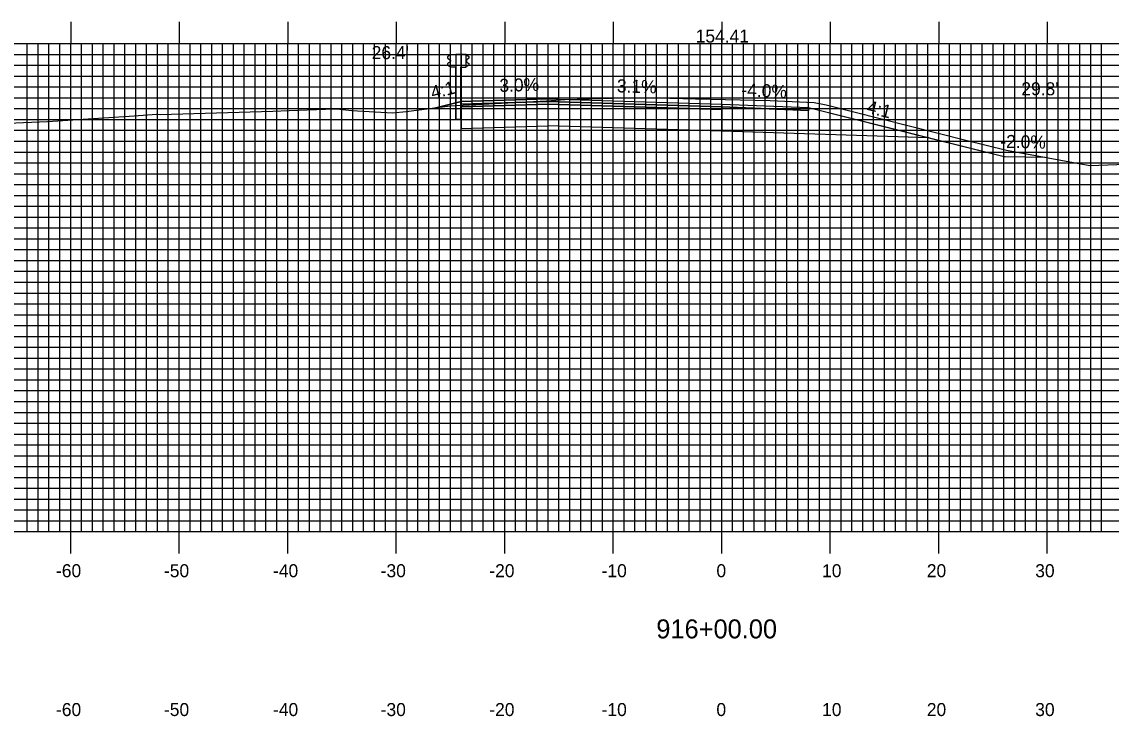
# Model space of a CAD drawing. Extents: x 861045 to 861388, y 364765 to 364985.
# Drawn here: x 861146.4 to 861246.8, y 364831.3 to 364895.3 of the extents above; entities that cross this region are included whole.
import ezdxf

# ---------------------------------------------------------------- set-up
doc = ezdxf.new("R2010")
doc.units = 0
for name, color, linetype in [('ANNOTATION', 7, 'Continuous'), ('D_Guardrail_Beam_Rt', 7, 'Continuous'), ('D_Roadway_Centerline', 7, 'Continuous'), ('D_Roadway_Centerline_Text', 7, 'Continuous'), ('D_Roadway_Edge_Shoulder', 7, 'Continuous'), ('D_Roadway_Edge_TW', 7, 'Continuous'), ('D_Roadway_Pavement', 7, 'Continuous'), ('D_Roadway_SlopeLines', 7, 'Continuous'), ('D_Roadway_SubGrade', 7, 'Continuous'), ('D_Text_Standard', 7, 'Continuous'), ('H_V ANNOTATION', 7, 'Continuous'), ('M_Guardrail', 7, 'Continuous'), ('M_Roadway_Centerline', 7, 'Continuous'), ('MAJOR', 7, 'Continuous'), ('MINOR', 7, 'Continuous'), ('S_Roadway_Centerline', 7, 'Continuous')]:
    doc.layers.add(name, color=color, linetype=linetype)

msp = doc.modelspace()

# ---------------------------------------------------------------- linework, layer by layer
at = {"layer": 'D_Guardrail_Beam_Rt'}
msp.add_line((861186.93, 364887.97), (861184.57, 364887.38), dxfattribs=at)
at = {"layer": 'D_Roadway_Centerline'}
msp.add_lwpolyline([(861184.57, 364887.38), (861186.93, 364887.97), (861189.93, 364888.06), (861194.93, 364888.21), (861194.93, 364888.21), (861210.93, 364887.71), (861218.93, 364887.39), (861219.43, 364887.27), (861230, 364884.62), (861230, 364884.62), (861236.97, 364882.88), (861237.05, 364882.88), (861240.75, 364882.81)], dxfattribs=at)
at = {"layer": 'D_Roadway_Edge_Shoulder'}
for points in [[(861194.93, 364888.21), (861189.93, 364888.06), (861186.93, 364887.97), (861186.93, 364887.72), (861194.93, 364887.96)], [(861210.93, 364887.71), (861218.93, 364887.39), (861218.93, 364887.14), (861210.93, 364887.46)]]:
    msp.add_lwpolyline(points, close=True, dxfattribs=at)
at = {"layer": 'D_Roadway_Edge_TW'}
msp.add_lwpolyline([(861194.93, 364888.21), (861210.93, 364887.71), (861210.93, 364887.46), (861194.93, 364887.96)], close=True, dxfattribs=at)
at = {"layer": 'D_Roadway_Pavement'}
for points in [[(861194.93, 364887.96), (861186.93, 364887.72), (861186.93, 364887.47), (861194.93, 364887.71)], [(861194.93, 364887.96), (861210.93, 364887.46), (861210.93, 364887.21), (861194.93, 364887.71)]]:
    msp.add_lwpolyline(points, close=True, dxfattribs=at)
msp.add_lwpolyline([(861210.93, 364887.46), (861210.93, 364887.21)], dxfattribs=at)
msp.add_lwpolyline([(861210.93, 364887.46), (861210.93, 364887.21)], dxfattribs=at)
at = {"layer": 'D_Roadway_SlopeLines'}
for points in [[(861218.93, 364887.39), (861236.97, 364882.88)], [(861236.97, 364882.88), (861240.75, 364882.81)]]:
    msp.add_lwpolyline(points, dxfattribs=at)
at = {"layer": 'D_Roadway_SubGrade'}
for points in [[(861194.93, 364887.71), (861186.93, 364887.47), (861186.93, 364887.72), (861186.93, 364885.47), (861194.93, 364885.71)], [(861194.93, 364887.71), (861210.93, 364887.21), (861210.93, 364885.21), (861194.93, 364885.71)], [(861210.93, 364887.21), (861210.93, 364887.46), (861218.93, 364887.14), (861218.93, 364887.39), (861230, 364884.62), (861210.93, 364885.21)]]:
    msp.add_lwpolyline(points, close=True, dxfattribs=at)
at = {"layer": 'M_Guardrail'}
for p, q in [((861185.83, 364892.19), (861185.69, 364892.09)), ((861185.69, 364891.95), (861185.88, 364891.81)), ((861185.88, 364891.59), (861185.69, 364891.46)), ((861185.93, 364892.21), (861185.85, 364892.2)), ((861185.92, 364891.75), (861185.92, 364891.66)), ((861185.93, 364892.29), (861186.42, 364892.29)), ((861185.93, 364891.12), (861185.93, 364892.29)), ((861186.41, 364892.29), (861186.41, 364886.29)), ((861186.9, 364892.29), (861186.41, 364892.29)), ((861186.42, 364892.29), (861186.91, 364892.29)), ((861186.42, 364892.29), (861186.42, 364891.12)), ((861187.39, 364892.29), (861186.9, 364892.29)), ((861186.9, 364892.29), (861186.9, 364891.12)), ((861186.91, 364892.29), (861186.91, 364886.29)), ((861187.39, 364891.12), (861187.39, 364892.29)), ((861187.39, 364892.21), (861187.47, 364892.2)), ((861187.4, 364891.75), (861187.4, 364891.66)), ((861187.63, 364891.95), (861187.43, 364891.81)), ((861187.43, 364891.59), (861187.63, 364891.46)), ((861187.49, 364892.19), (861187.63, 364892.09)), ((861185.69, 364891.31), (861185.83, 364891.21)), ((861185.85, 364891.21), (861185.93, 364891.19)), ((861186.42, 364891.12), (861185.93, 364891.12)), ((861186.42, 364886.29), (861186.42, 364891.12)), ((861186.9, 364886.29), (861186.9, 364891.12)), ((861186.9, 364891.12), (861187.39, 364891.12)), ((861187.47, 364891.21), (861187.39, 364891.19)), ((861187.63, 364891.32), (861187.49, 364891.22)), ((861186.9, 364886.29), (861186.41, 364886.29)), ((861186.42, 364886.29), (861186.91, 364886.29))]:
    msp.add_line(p, q, dxfattribs=at)
for centre, major_axis, start_param, end_param in [((861185.74, 364892.02), (-0.0877, 0), 5.323254, 7.243116), ((861185.85, 364892.16), (-0.0417, 0), 4.886922, 5.323254), ((861185.84, 364891.75), (0.0789, 0), 0, 0.959931), ((861185.84, 364891.66), (0.0789, 0), 5.323254, 6.283185), ((861187.48, 364891.75), (-0.0789, 0), 5.323254, 6.283185), ((861187.48, 364891.66), (-0.0789, 0), 6.283185, 7.243116), ((861187.46, 364892.16), (0.0417, 0), 0.959931, 1.396263), ((861187.58, 364892.02), (0.0877, 0), 5.323254, 7.243116), ((861185.74, 364891.39), (-0.0877, 0), 5.323254, 7.243116), ((861185.85, 364891.25), (-0.0417, 0), 0.959931, 1.396263), ((861187.46, 364891.25), (0.0417, 0), 4.886922, 5.323254), ((861187.58, 364891.39), (0.0877, 0), 5.323254, 7.243116)]:
    msp.add_ellipse(centre, major_axis=major_axis, ratio=0.995501, start_param=start_param, end_param=end_param, dxfattribs=at)
at = {"layer": 'MAJOR'}
for p, q in [((861150.93, 364895.31), (861150.93, 364893.3)), ((861160.93, 364895.31), (861160.93, 364893.3)), ((861170.93, 364895.31), (861170.93, 364893.3)), ((861180.93, 364895.31), (861180.93, 364893.3)), ((861190.93, 364895.31), (861190.93, 364893.3)), ((861200.93, 364895.31), (861200.93, 364893.3)), ((861210.93, 364895.31), (861210.93, 364893.3)), ((861220.93, 364895.31), (861220.93, 364893.3)), ((861230.93, 364895.31), (861230.93, 364893.3)), ((861240.93, 364895.31), (861240.93, 364893.3)), ((861070.93, 364893.3), (861350.93, 364893.3)), ((861070.93, 364893.3), (861350.93, 364893.3)), ((861150.93, 364848.3), (861150.93, 364893.3)), ((861160.93, 364848.3), (861160.93, 364893.3)), ((861170.93, 364848.3), (861170.93, 364893.3)), ((861180.93, 364848.3), (861180.93, 364893.3)), ((861190.93, 364848.3), (861190.93, 364893.3)), ((861200.93, 364848.3), (861200.93, 364893.3)), ((861210.93, 364848.3), (861210.93, 364893.3)), ((861220.93, 364848.3), (861220.93, 364893.3)), ((861230.93, 364848.3), (861230.93, 364893.3)), ((861240.93, 364848.3), (861240.93, 364893.3)), ((861070.93, 364888.3), (861350.93, 364888.3)), ((861070.93, 364883.3), (861350.93, 364883.3)), ((861070.93, 364878.3), (861350.93, 364878.3)), ((861070.93, 364873.3), (861350.93, 364873.3)), ((861070.93, 364868.3), (861350.93, 364868.3)), ((861070.93, 364863.3), (861350.93, 364863.3)), ((861070.93, 364858.3), (861350.93, 364858.3)), ((861070.93, 364853.3), (861350.93, 364853.3)), ((861070.93, 364848.3), (861350.93, 364848.3)), ((861070.93, 364848.3), (861350.93, 364848.3)), ((861150.93, 364846.3), (861150.93, 364848.3)), ((861160.93, 364846.3), (861160.93, 364848.3)), ((861170.93, 364846.3), (861170.93, 364848.3)), ((861180.93, 364846.3), (861180.93, 364848.3)), ((861190.93, 364846.3), (861190.93, 364848.3)), ((861200.93, 364846.3), (861200.93, 364848.3)), ((861210.93, 364846.3), (861210.93, 364848.3)), ((861220.93, 364846.3), (861220.93, 364848.3)), ((861230.93, 364846.3), (861230.93, 364848.3)), ((861240.93, 364846.3), (861240.93, 364848.3))]:
    msp.add_line(p, q, dxfattribs=at)
at = {"layer": 'MINOR'}
for p, q in [((861146.93, 364848.3), (861146.93, 364893.3)), ((861147.93, 364848.3), (861147.93, 364893.3)), ((861148.93, 364848.3), (861148.93, 364893.3)), ((861149.93, 364848.3), (861149.93, 364893.3)), ((861151.93, 364848.3), (861151.93, 364893.3)), ((861152.93, 364848.3), (861152.93, 364893.3)), ((861153.93, 364848.3), (861153.93, 364893.3)), ((861154.93, 364848.3), (861154.93, 364893.3)), ((861155.93, 364848.3), (861155.93, 364893.3)), ((861156.93, 364848.3), (861156.93, 364893.3)), ((861157.93, 364848.3), (861157.93, 364893.3)), ((861158.93, 364848.3), (861158.93, 364893.3)), ((861159.93, 364848.3), (861159.93, 364893.3)), ((861161.93, 364848.3), (861161.93, 364893.3)), ((861162.93, 364848.3), (861162.93, 364893.3)), ((861163.93, 364848.3), (861163.93, 364893.3)), ((861164.93, 364848.3), (861164.93, 364893.3)), ((861165.93, 364848.3), (861165.93, 364893.3)), ((861166.93, 364848.3), (861166.93, 364893.3)), ((861167.93, 364848.3), (861167.93, 364893.3)), ((861168.93, 364848.3), (861168.93, 364893.3)), ((861169.93, 364848.3), (861169.93, 364893.3)), ((861171.93, 364848.3), (861171.93, 364893.3)), ((861172.93, 364848.3), (861172.93, 364893.3)), ((861173.93, 364848.3), (861173.93, 364893.3)), ((861174.93, 364848.3), (861174.93, 364893.3)), ((861175.93, 364848.3), (861175.93, 364893.3)), ((861176.93, 364848.3), (861176.93, 364893.3)), ((861177.93, 364848.3), (861177.93, 364893.3)), ((861178.93, 364848.3), (861178.93, 364893.3)), ((861179.93, 364848.3), (861179.93, 364893.3)), ((861181.93, 364848.3), (861181.93, 364893.3)), ((861182.93, 364848.3), (861182.93, 364893.3)), ((861183.93, 364848.3), (861183.93, 364893.3)), ((861184.93, 364848.3), (861184.93, 364893.3)), ((861185.93, 364848.3), (861185.93, 364893.3)), ((861186.93, 364848.3), (861186.93, 364893.3)), ((861187.93, 364848.3), (861187.93, 364893.3)), ((861188.93, 364848.3), (861188.93, 364893.3)), ((861189.93, 364848.3), (861189.93, 364893.3)), ((861191.93, 364848.3), (861191.93, 364893.3)), ((861192.93, 364848.3), (861192.93, 364893.3)), ((861193.93, 364848.3), (861193.93, 364893.3)), ((861194.93, 364848.3), (861194.93, 364893.3)), ((861195.93, 364848.3), (861195.93, 364893.3)), ((861196.93, 364848.3), (861196.93, 364893.3)), ((861197.93, 364848.3), (861197.93, 364893.3)), ((861198.93, 364848.3), (861198.93, 364893.3)), ((861199.93, 364848.3), (861199.93, 364893.3)), ((861201.93, 364848.3), (861201.93, 364893.3)), ((861202.93, 364848.3), (861202.93, 364893.3)), ((861203.93, 364848.3), (861203.93, 364893.3)), ((861204.93, 364848.3), (861204.93, 364893.3)), ((861205.93, 364848.3), (861205.93, 364893.3)), ((861206.93, 364848.3), (861206.93, 364893.3)), ((861207.93, 364848.3), (861207.93, 364893.3)), ((861208.93, 364848.3), (861208.93, 364893.3)), ((861209.93, 364848.3), (861209.93, 364893.3)), ((861211.93, 364848.3), (861211.93, 364893.3)), ((861212.93, 364848.3), (861212.93, 364893.3)), ((861213.93, 364848.3), (861213.93, 364893.3)), ((861214.93, 364848.3), (861214.93, 364893.3)), ((861215.93, 364848.3), (861215.93, 364893.3)), ((861216.93, 364848.3), (861216.93, 364893.3)), ((861217.93, 364848.3), (861217.93, 364893.3)), ((861218.93, 364848.3), (861218.93, 364893.3)), ((861219.93, 364848.3), (861219.93, 364893.3)), ((861221.93, 364848.3), (861221.93, 364893.3)), ((861222.93, 364848.3), (861222.93, 364893.3)), ((861223.93, 364848.3), (861223.93, 364893.3)), ((861224.93, 364848.3), (861224.93, 364893.3)), ((861225.93, 364848.3), (861225.93, 364893.3)), ((861226.93, 364848.3), (861226.93, 364893.3)), ((861227.93, 364848.3), (861227.93, 364893.3)), ((861228.93, 364848.3), (861228.93, 364893.3)), ((861229.93, 364848.3), (861229.93, 364893.3)), ((861231.93, 364848.3), (861231.93, 364893.3)), ((861232.93, 364848.3), (861232.93, 364893.3)), ((861233.93, 364848.3), (861233.93, 364893.3)), ((861234.93, 364848.3), (861234.93, 364893.3)), ((861235.93, 364848.3), (861235.93, 364893.3)), ((861236.93, 364848.3), (861236.93, 364893.3)), ((861237.93, 364848.3), (861237.93, 364893.3)), ((861238.93, 364848.3), (861238.93, 364893.3)), ((861239.93, 364848.3), (861239.93, 364893.3)), ((861241.93, 364848.3), (861241.93, 364893.3)), ((861242.93, 364848.3), (861242.93, 364893.3)), ((861243.93, 364848.3), (861243.93, 364893.3)), ((861244.93, 364848.3), (861244.93, 364893.3)), ((861245.93, 364848.3), (861245.93, 364893.3)), ((861070.93, 364892.3), (861350.93, 364892.3)), ((861070.93, 364891.3), (861350.93, 364891.3)), ((861070.93, 364890.3), (861350.93, 364890.3)), ((861070.93, 364889.3), (861350.93, 364889.3)), ((861070.93, 364887.3), (861350.93, 364887.3)), ((861070.93, 364886.3), (861350.93, 364886.3)), ((861070.93, 364885.3), (861350.93, 364885.3)), ((861070.93, 364884.3), (861350.93, 364884.3)), ((861070.93, 364882.3), (861350.93, 364882.3)), ((861070.93, 364881.3), (861350.93, 364881.3)), ((861070.93, 364880.3), (861350.93, 364880.3)), ((861070.93, 364879.3), (861350.93, 364879.3)), ((861070.93, 364877.3), (861350.93, 364877.3)), ((861070.93, 364876.3), (861350.93, 364876.3)), ((861070.93, 364875.3), (861350.93, 364875.3)), ((861070.93, 364874.3), (861350.93, 364874.3)), ((861070.93, 364872.3), (861350.93, 364872.3)), ((861070.93, 364871.3), (861350.93, 364871.3)), ((861070.93, 364870.3), (861350.93, 364870.3)), ((861070.93, 364869.3), (861350.93, 364869.3)), ((861070.93, 364867.3), (861350.93, 364867.3)), ((861070.93, 364866.3), (861350.93, 364866.3)), ((861070.93, 364865.3), (861350.93, 364865.3)), ((861070.93, 364864.3), (861350.93, 364864.3)), ((861070.93, 364862.3), (861350.93, 364862.3)), ((861070.93, 364861.3), (861350.93, 364861.3)), ((861070.93, 364860.3), (861350.93, 364860.3)), ((861070.93, 364859.3), (861350.93, 364859.3)), ((861070.93, 364857.3), (861350.93, 364857.3)), ((861070.93, 364856.3), (861350.93, 364856.3)), ((861070.93, 364855.3), (861350.93, 364855.3)), ((861070.93, 364854.3), (861350.93, 364854.3)), ((861070.93, 364852.3), (861350.93, 364852.3)), ((861070.93, 364851.3), (861350.93, 364851.3)), ((861070.93, 364850.3), (861350.93, 364850.3)), ((861070.93, 364849.3), (861350.93, 364849.3))]:
    msp.add_line(p, q, dxfattribs=at)
at = {"layer": 'S_Roadway_Centerline'}
msp.add_lwpolyline([(861143.63, 364885.9), (861148.8, 364886.1), (861156.79, 364886.63), (861158.84, 364886.79), (861159.17, 364886.77), (861169.57, 364887.08), (861171.08, 364887.14), (861174.42, 364887.25), (861175.47, 364887.28), (861176.83, 364887.14), (861180.6, 364886.92), (861181.86, 364887.04), (861185.91, 364887.55), (861194.79, 364888.01), (861196.51, 364888.15), (861200.95, 364888.27), (861204.67, 364888.3), (861204.98, 364888.28), (861208.5, 364888.2), (861215.38, 364888.05), (861219.46, 364887.86), (861220.54, 364887.65), (861233.42, 364884.39), (861237.18, 364883.46), (861244.85, 364882.06), (861249.82, 364882.25)], dxfattribs=at)

# ---------------------------------------------------------------- texts
at = {"layer": 'ANNOTATION'}
for s, rotation, p in [('4:1', 14.0362, (861184.28, 364888.17)), ('-3.0%', 1.7183, (861189.92, 364888.82)), ('3.1%', 358.2316, (861201.25, 364888.81)), ('-4.0%', 357.7094, (861212.72, 364888.44)), ('4:1', 345.9627, (861224.22, 364886.93)), ('-2.0%', 358.8634, (861236.59, 364883.69))]:
    msp.add_text(s, height=1.2, rotation=rotation, dxfattribs=at).set_placement(p)
at = {"layer": 'D_Roadway_Centerline_Text'}
msp.add_text('154.41', height=1.2, dxfattribs=at).set_placement((861208.53, 364893.39))
at = {"layer": 'D_Text_Standard'}
for s, p in [("26.4'", (861178.67, 364891.86)), ("29.8'", (861238.54, 364888.53))]:
    msp.add_text(s, height=1.2, dxfattribs=at).set_placement(p)
at = {"layer": 'H_V ANNOTATION'}
for s, height, p in [('-60', 1.2, (861149.58, 364844.1)), ('-50', 1.2, (861159.53, 364844.1)), ('-40', 1.2, (861169.58, 364844.1)), ('-30', 1.2, (861179.5, 364844.1)), ('-20', 1.2, (861189.51, 364844.1)), ('-10', 1.2, (861199.86, 364844.1)), ('0', 1.2, (861210.44, 364844.1)), ('10', 1.2, (861220.18, 364844.1)), ('20', 1.2, (861229.83, 364844.1)), ('30', 1.2, (861239.82, 364844.1)), ('916+00.00', 1.75, (861204.9, 364838.46)), ('-60', 1.2, (861149.58, 364831.3)), ('-50', 1.2, (861159.53, 364831.3)), ('-40', 1.2, (861169.58, 364831.3)), ('-30', 1.2, (861179.5, 364831.3)), ('-20', 1.2, (861189.51, 364831.3)), ('-10', 1.2, (861199.86, 364831.3)), ('0', 1.2, (861210.44, 364831.3)), ('10', 1.2, (861220.18, 364831.3)), ('20', 1.2, (861229.83, 364831.3)), ('30', 1.2, (861239.82, 364831.3))]:
    msp.add_text(s, height=height, dxfattribs=at).set_placement(p)
at = {"layer": 'M_Roadway_Centerline'}
for s, p in [('C', (861204.66, 364888.3)), ('L', (861204.67, 364888.29)), ('C', (861158.84, 364886.79)), ('L', (861158.84, 364886.79))]:
    msp.add_text(s, height=0.0146, dxfattribs=at).set_placement(p)

doc.saveas('drawing.dxf')
